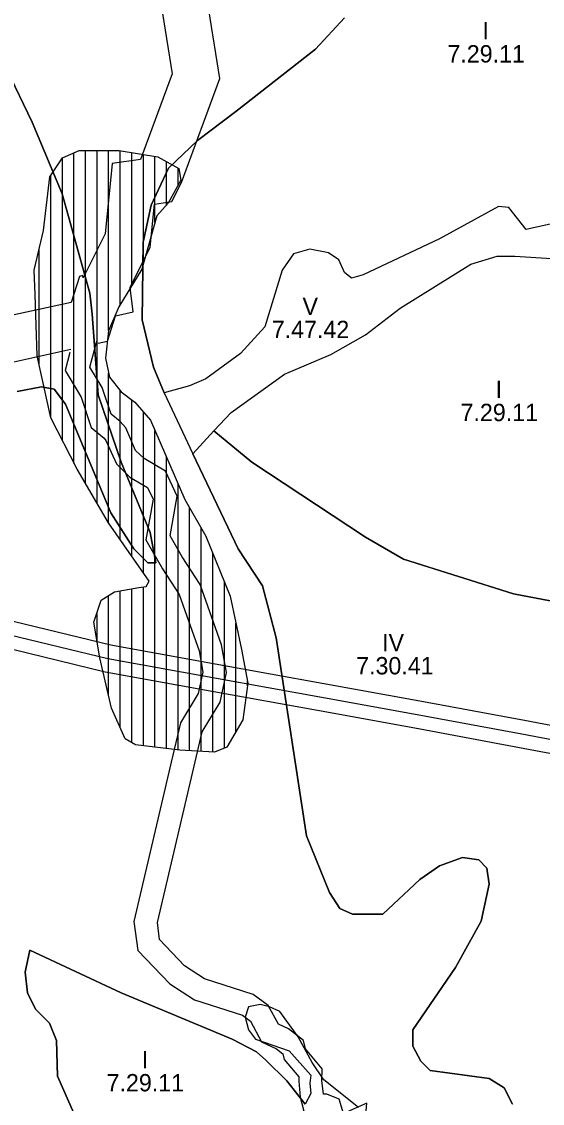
# Model space of a CAD drawing. Extents: x -694504 to -690518, y -983661 to -978958.
# Drawn here: x -693268 to -692818, y -981518 to -980583 of the extents above; entities that cross this region are included whole.
import ezdxf

# ---------------------------------------------------------------- set-up
doc = ezdxf.new("R2010")
doc.units = 0
for name, color, linetype in [('BPEJ', 7, 'Continuous'), ('lokální biokoridory', 7, 'Continuous'), ('nadregionální biokoridor', 7, 'Continuous'), ('ochranné pásmo vedení', 7, 'Continuous'), ('odvodněné pozemky', 7, 'Continuous'), ('třídy přednosti v ochraně ZP', 7, 'Continuous'), ('vedení VN 35kV', 7, 'Continuous')]:
    doc.layers.add(name, color=color, linetype=linetype)

msp = doc.modelspace()

# ---------------------------------------------------------------- linework, layer by layer
at = {"layer": 'BPEJ'}
for points in [[(-692805.4, -980756.81), (-692832.4, -980762.81), (-692847.4, -980743.81), (-692856.4, -980742.81), (-692907.4, -980770.81), (-692973.4, -980801.81), (-692983.4, -980804.81), (-692989.4, -980799.81), (-692994.4, -980788.81), (-693003.4, -980782.81), (-693019.4, -980779.81), (-693033.4, -980783.81), (-693043.4, -980797.81), (-693058.4, -980846.81), (-693079.4, -980869.81), (-693109.4, -980891.81), (-693123.4, -980897.81), (-693145.4, -980903.81), (-693154.4, -980881.81), (-693164.4, -980840.81), (-693163.4, -980773.81), (-693156.4, -980741.81), (-693141.4, -980709.81), (-693116.4, -980685.81), (-693083.4, -980660.81), (-693014.4, -980606.81), (-692989.4, -980579.81)], [(-692989.4, -980579.81), (-693014.4, -980606.81), (-693083.4, -980660.81), (-693116.4, -980685.81), (-693141.4, -980709.81), (-693156.4, -980741.81), (-693163.4, -980773.81), (-693164.4, -980840.81), (-693154.4, -980881.81), (-693145.4, -980903.81), (-693120.4, -980956.81), (-693081.4, -981038.81), (-693060.4, -981070.81), (-693048.4, -981115.81), (-693022.4, -981286.81), (-693002.4, -981335.81), (-692993.4, -981349.81), (-692982.4, -981354.81), (-692956.4, -981354.81), (-692924.4, -981324.81), (-692907.4, -981312.81), (-692887.4, -981305.81), (-692873.4, -981307.81), (-692866.4, -981314.81), (-692864.4, -981328.81), (-692871.4, -981360.81), (-692893.4, -981400.81), (-692930.4, -981454.81), (-692930.4, -981468.81), (-692923.4, -981481.81), (-692915.4, -981489.81), (-692864.4, -981496.81), (-692851.4, -981504.81), (-692844.4, -981518.81)], [(-693272.4, -980902.81), (-693251.4, -980898.81), (-693240.4, -980900.81), (-693230.4, -980913.81), (-693191.4, -981007.81), (-693171.4, -981038.81), (-693159.4, -981050.81), (-693152.4, -981050.81), (-693157.4, -981024.81), (-693182.4, -980963.81), (-693202.4, -980905.81), (-693207.4, -980835.81), (-693209.4, -980817.81), (-693224.4, -980763.81), (-693233.4, -980731.81), (-693259.4, -980669.81), (-693281.4, -980623.81)], [(-693281.4, -980623.81), (-693259.4, -980669.81), (-693233.4, -980731.81), (-693224.4, -980763.81), (-693209.4, -980817.81), (-693207.4, -980835.81), (-693202.4, -980905.81), (-693182.4, -980963.81), (-693157.4, -981024.81), (-693152.4, -981050.81), (-693159.4, -981050.81), (-693171.4, -981038.81), (-693191.4, -981007.81), (-693230.4, -980913.81), (-693240.4, -980900.81), (-693251.4, -980898.81), (-693272.4, -980902.81)], [(-692754.4, -981094.81), (-692843.4, -981077.81), (-692938.4, -981047.81), (-692971.4, -981028.81), (-693069.4, -980963.81), (-693102.4, -980936.81), (-693087.4, -980920.81), (-693041.4, -980887.81), (-693001.4, -980870.81), (-692971.4, -980853.81), (-692941.4, -980830.81), (-692880.4, -980792.81), (-692857.4, -980785.81), (-692842.4, -980785.81), (-692810.4, -980787.81)], [(-693048.4, -981115.81), (-693060.4, -981070.81), (-693081.4, -981038.81), (-693120.4, -980956.81), (-693102.4, -980936.81), (-693069.4, -980963.81), (-692971.4, -981028.81), (-692938.4, -981047.81), (-692843.4, -981077.81), (-692754.4, -981094.81), (-692685.4, -981109.81), (-692677.4, -981113.81), (-692662.4, -981119.81), (-692649.4, -981132.81), (-692631.4, -981153.81), (-692615.4, -981196.81), (-692615.4, -981196.81)], [(-692844.4, -981518.81), (-692851.4, -981504.81), (-692864.4, -981496.81), (-692915.4, -981489.81), (-692923.4, -981481.81), (-692930.4, -981468.81), (-692930.4, -981454.81), (-692893.4, -981400.81), (-692871.4, -981360.81), (-692864.4, -981328.81), (-692866.4, -981314.81), (-692873.4, -981307.81), (-692887.4, -981305.81), (-692907.4, -981312.81), (-692924.4, -981324.81), (-692956.4, -981354.81), (-692982.4, -981354.81), (-692993.4, -981349.81), (-693002.4, -981335.81), (-693022.4, -981286.81), (-693048.4, -981115.81)], [(-692977.4, -981521.81), (-693007.4, -981497.81), (-693017.4, -981482.81), (-693029.4, -981460.81), (-693045.4, -981438.81), (-693054.4, -981434.81), (-693062.4, -981432.81), (-693072.4, -981434.81), (-693075.4, -981443.81), (-693072.4, -981454.81), (-693066.4, -981462.81), (-693037.4, -981472.81), (-693018.4, -981493.81), (-693019.4, -981500.81), (-693018.4, -981509.81), (-693023.4, -981518.81), (-693039.4, -981498.81), (-693057.4, -981480.81), (-693065.4, -981473.81), (-693086.4, -981462.81), (-693182.4, -981422.81), (-693261.4, -981385.81), (-693265.4, -981404.81), (-693263.4, -981422.81), (-693256.4, -981436.81), (-693244.4, -981448.81), (-693238.4, -981463.81), (-693237.4, -981494.81), (-693223.4, -981526.81)], [(-693223.4, -981526.81), (-693237.4, -981494.81), (-693238.4, -981463.81), (-693244.4, -981448.81), (-693256.4, -981436.81), (-693263.4, -981422.81), (-693265.4, -981404.81), (-693261.4, -981385.81), (-693182.4, -981422.81), (-693086.4, -981462.81), (-693065.4, -981473.81), (-693057.4, -981480.81), (-693039.4, -981498.81), (-693023.4, -981518.81)]]:
    msp.add_lwpolyline(points, dxfattribs=at)
at = {"layer": 'lokální biokoridory'}
for points in [[(-692972.33, -981545.5), (-692970.02, -981518.09), (-692990.3, -981527.14), (-692994.16, -981514.73), (-693004.75, -981510.28), (-693007.66, -981510.33), (-693009.01, -981498.37), (-693008.64, -981488.37), (-693023.16, -981471.17), (-693024.78, -981463.78), (-693037.92, -981453.9), (-693046.57, -981449.84), (-693055.36, -981433.6), (-693068.47, -981424.04), (-693110.52, -981410.52), (-693127.63, -981399.38), (-693149.34, -981376.54), (-693151.09, -981361.88), (-693132.31, -981282.09), (-693119.68, -981227.84), (-693112.31, -981196.9), (-693096.92, -981171.29), (-693091.38, -981145.68), (-693095.75, -981121.92), (-693114.31, -981069.58), (-693129.62, -981045.61), (-693140.07, -981027.43), (-693134.1, -980993.26), (-693144.06, -980971.6), (-693162.64, -980960.68), (-693169.91, -980953.71), (-693178.47, -980934.31), (-693183.22, -980928.8), (-693191.19, -980922.24), (-693198.75, -980899.3), (-693209.38, -980881.63), (-693203.33, -980859.13)], [(-693226.7, -980869.01), (-693230.9, -980884.64), (-693217.04, -980907.69), (-693208.37, -980933.99), (-693197.26, -980943.15), (-693195.57, -980945.11), (-693186.6, -980965.41), (-693174.8, -980976.74), (-693159.61, -980985.66), (-693154.88, -980995.96), (-693161.02, -981031.12), (-693146.73, -981055.99), (-693132.4, -981078.42), (-693115.13, -981127.11), (-693111.77, -981145.36), (-693115.77, -981163.83), (-693131.05, -981189.25), (-693139.15, -981223.26), (-693151.78, -981277.53), (-693171.4, -981360.88), (-693168.02, -981386.18), (-693140.47, -981414.89), (-693119.18, -981428.74), (-693077.65, -981442.1), (-693070.79, -981447.1), (-693061.03, -981465.14), (-693048.29, -981471.13), (-693042.73, -981475.3), (-693041.64, -981480.28), (-693028.91, -981495.36), (-693029.05, -981499.02), (-693027.62, -981512.92), (-693023.26, -981530.56)]]:
    msp.add_lwpolyline(points, dxfattribs=at)
at = {"layer": 'nadregionální biokoridor'}
for points in [[(-692976.88, -980387.74), (-693001, -980423.8), (-693051.69, -980447.88), (-693086.28, -980481.45), (-693108.83, -980506.94), (-693122.82, -980518.78), (-693146.81, -980554.13), (-693146.81, -980575.87), (-693138.39, -980628.27), (-693165.64, -980702.13), (-693190.13, -980705.8), (-693196.33, -980766.6), (-693215.28, -980804.51), (-693215.47, -980802.6), (-693218.38, -980803.25), (-693225.6, -980825.71), (-693359.08, -980854.74), (-693655.15, -980918.88), (-693662.19, -980917.18), (-693662.19, -980917.18), (-693662.19, -980917.18)], [(-693202.36, -980861.12), (-693194.24, -980859.32), (-693187.24, -980837.3), (-693172.14, -980833.95), (-693174.53, -980812.97), (-693157.28, -980777.94), (-693153.49, -980740.75), (-693138.57, -980738.51), (-693130.43, -980722.23), (-693097.23, -980632.28), (-693106.81, -980572.68), (-693106.81, -980566.42), (-693092.8, -980545.77), (-693080.79, -980535.61), (-693057.33, -980509.1), (-693023.92, -980476.67), (-693001.24, -980454.94), (-692973.56, -980436.48), (-692942.12, -980419.83), (-692917.27, -980412.19), (-692899.78, -980405.46)], [(-693669.34, -980956.96), (-693654.47, -980959.66), (-693350.54, -980893.81), (-693225.99, -980866.33)]]:
    msp.add_lwpolyline(points, dxfattribs=at)
at = {"layer": 'ochranné pásmo vedení'}
for points in [[(-692739.96, -981204.97), (-692834.02, -981187.35), (-692924.48, -981170.45), (-693008.63, -981155.22), (-693098.05, -981139.02), (-693191.42, -981122.13), (-693284.2, -981099.61), (-693356.17, -981083.19), (-693481.9, -981059.5), (-693556.87, -981044.56), (-693628.51, -981033.31), (-693671.51, -981026.82), (-693666.81, -980992.3), (-693660.61, -980936.24), (-693644.3, -980827.21), (-693633.59, -980721.11), (-693628.19, -980683.5)], [(-693431.59, -981319.12), (-693410.32, -981249.12), (-693390.88, -981197.91), (-693367.08, -981143.25), (-693351.72, -981108.31), (-693289.59, -981122.49), (-693196.29, -981145.13), (-693102.23, -981162.14), (-693012.81, -981178.34), (-692928.73, -981193.56), (-692838.35, -981210.45), (-692744.28, -981228.07)]]:
    msp.add_lwpolyline(points, dxfattribs=at)
at = {"layer": 'odvodněné pozemky'}
for p, q in [((-693233.25, -980945.22), (-693233.25, -980700.89)), ((-693223.25, -980964.83), (-693223.25, -980696.51)), ((-693213.25, -980982.53), (-693213.25, -980694.54)), ((-693203.25, -980999.54), (-693203.25, -980694.54)), ((-693193.25, -980850.12), (-693193.25, -980694.54)), ((-693183.25, -980827.81), (-693183.25, -980694.71)), ((-693173.25, -980811.46), (-693173.25, -980696.33)), ((-693163.25, -980792.67), (-693163.25, -980697.95)), ((-693153.25, -980756.54), (-693153.25, -980699.58)), ((-693143.25, -980741.61), (-693143.25, -980704.11)), ((-693133.25, -980724.43), (-693133.25, -980709.61)), ((-693243.25, -980925.61), (-693243.25, -980715.89)), ((-693253.25, -980880.21), (-693253.25, -980779.02)), ((-693193.25, -981016.51), (-693193.25, -980886.8)), ((-693183.25, -981030.85), (-693183.25, -980902.03)), ((-693173.25, -981045.2), (-693173.25, -980910.09)), ((-693163.25, -981059.54), (-693163.25, -980920.52)), ((-693153.25, -981210.38), (-693153.25, -980936.4)), ((-693143.25, -981211.58), (-693143.25, -980959.45)), ((-693133.25, -981212.77), (-693133.25, -980982.49)), ((-693123.25, -981213.46), (-693123.25, -981003.29)), ((-693113.25, -981214.06), (-693113.25, -981020.8)), ((-693103.25, -981214.67), (-693103.25, -981042.62)), ((-693093.25, -981211.14), (-693093.25, -981067.42)), ((-693183.25, -981193.43), (-693183.25, -981075.12)), ((-693173.25, -981206.4), (-693173.25, -981073.38)), ((-693163.25, -981209.19), (-693163.25, -981071.77)), ((-693193.25, -981165.82), (-693193.25, -981079.16)), ((-693203.25, -981118.89), (-693203.25, -981093.46)), ((-693083.25, -981196.71), (-693083.25, -981103.16)), ((-693073.25, -981157.36), (-693073.25, -981153.1))]:
    msp.add_line(p, q, dxfattribs=at)
for points in [[(-693244.13, -980717.22), (-693233.25, -980700.89), (-693218.74, -980694.54), (-693184.29, -980694.54), (-693150.75, -980699.98), (-693132.61, -980709.96), (-693130.8, -980719.94), (-693141.68, -980739.9), (-693151.65, -980750.78), (-693164.48, -980797.12)], [(-693256.82, -980818.82), (-693257.73, -980797.95), (-693249.57, -980763.48), (-693244.13, -980717.22)], [(-693164.48, -980797.12), (-693184.31, -980829.54), (-693193.37, -980850.41), (-693196.09, -980873.99), (-693192.47, -980890.32), (-693182.52, -980902.96), (-693170.73, -980912.03), (-693157.13, -980927.45), (-693127.3, -980996.2), (-693109.17, -981027.95), (-693088.32, -981079.65), (-693078.34, -981125.92), (-693072.9, -981154.94), (-693077.44, -981186.63), (-693091.04, -981210.21), (-693101.92, -981214.75), (-693131.84, -981212.94), (-693169.92, -981208.4), (-693178.98, -981202.96), (-693190.77, -981176.65), (-693200.74, -981133.11), (-693206.18, -981102.27), (-693199.83, -981083.21), (-693188.05, -981075.96), (-693167.2, -981072.33), (-693160.85, -981071.42), (-693158.13, -981066.89), (-693193.39, -981016.31), (-693220.59, -980970.05), (-693243.26, -980925.6), (-693255.04, -980872.08), (-693256.82, -980818.82)]]:
    msp.add_lwpolyline(points, dxfattribs=at)
at = {"layer": 'vedení VN 35kV'}
msp.add_lwpolyline([(-693684.71, -981036.71), (-693630.3, -981044.93), (-693558.93, -981056.13), (-693484.13, -981071.04), (-693358.57, -981094.7), (-693286.9, -981111.05), (-693193.86, -981133.63), (-693100.14, -981150.58), (-693010.72, -981166.78), (-692926.61, -981182), (-692836.19, -981198.9), (-692742.12, -981216.52)], dxfattribs=at)

# ---------------------------------------------------------------- texts
at = {"layer": 'třídy přednosti v ochraně ZP'}
for s, p in [('I', (-692870.2, -980598.35)), ('7.29.11', (-692900.51, -980618.35)), ('V', (-693025.72, -980836.65)), ('7.47.42', (-693052.27, -980856.65)), ('I', (-692858.86, -980908.41)), ('7.29.11', (-692889.17, -980928.41)), ('IV', (-692956.93, -981127.36)), ('7.30.41', (-692979.38, -981147.36)), ('I', (-693164.69, -981487.89)), ('7.29.11', (-693195, -981507.89))]:
    msp.add_text(s, height=15, dxfattribs=at).set_placement(p)

doc.saveas('drawing.dxf')
